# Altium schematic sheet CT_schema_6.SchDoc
size 278 x 170 mm
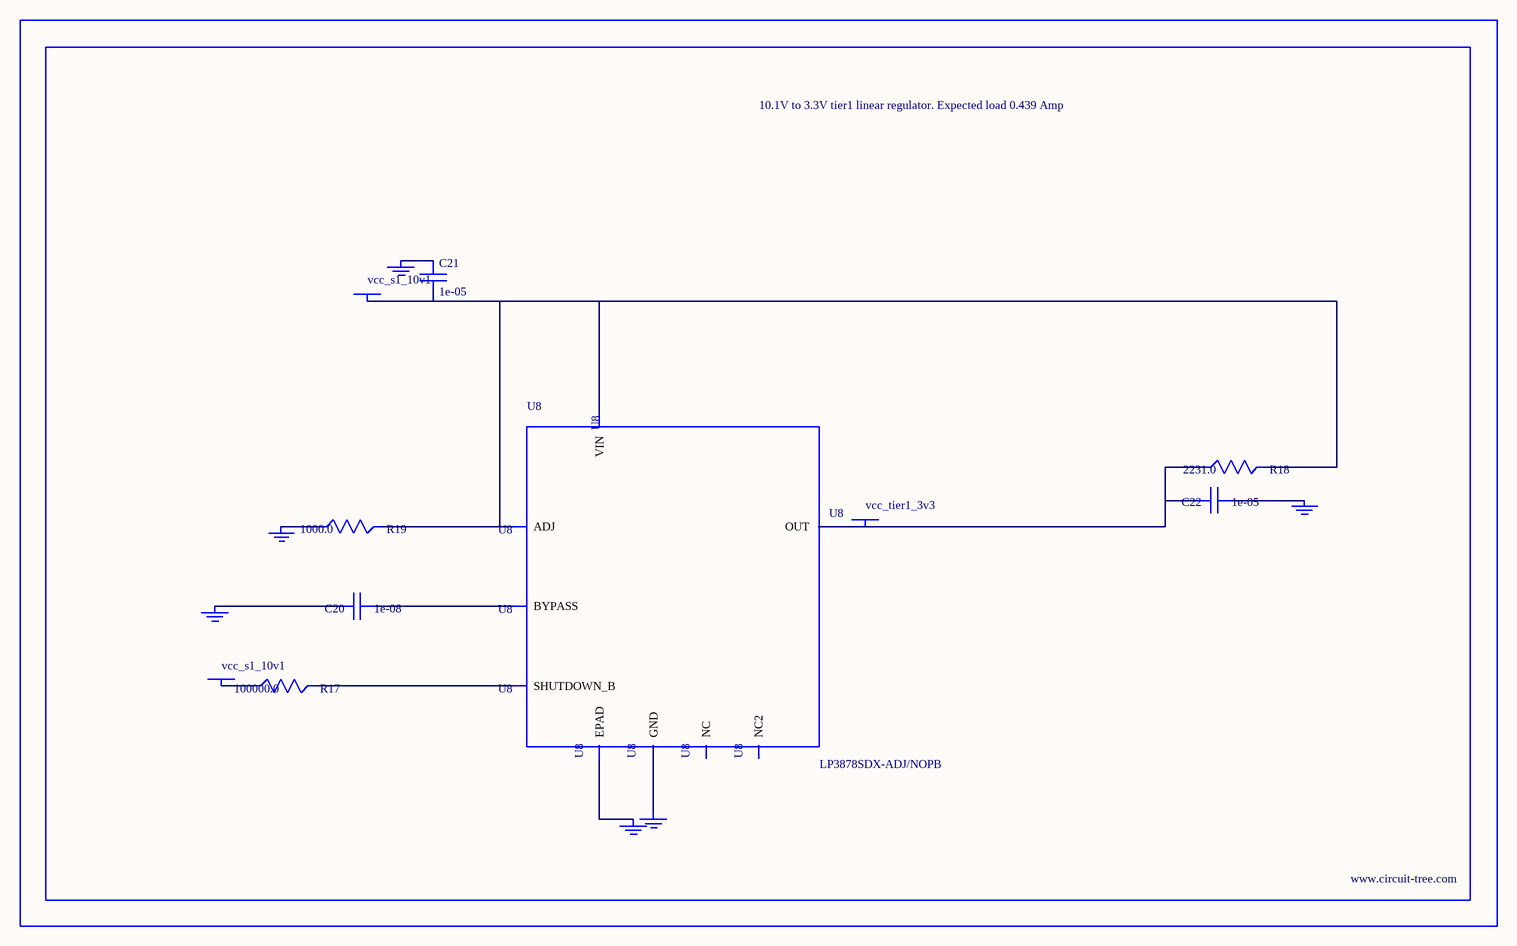
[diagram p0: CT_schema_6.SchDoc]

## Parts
BORDER5  (no value)
C20  1e-08  [C0402]
C21  1e-05  [C1206]
C22  1e-05  [C1210]
GND_INSTANCE_5_0  (no value)
GND_INSTANCE_5_1  (no value)
GND_INSTANCE_5_2  (no value)
GND_INSTANCE_5_3  (no value)
GND_INSTANCE_5_4  (no value)
GND_INSTANCE_5_5  (no value)
POWER_INSTANCE_5_0  vcc_s1_10v1
POWER_INSTANCE_5_1  vcc_s1_10v1
POWER_INSTANCE_5_2  vcc_tier1_3v3
R17  100000.0  [R0603]
R18  2231.0  [R0603]
R19  1000.0  [R0603]
U8  LP3878SDX-ADJ/NOPB  [WSON-8]

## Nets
NetC20_1: C20.1 U8.1(BYPASS)
NetC20_2: C20.2 GND_INSTANCE_5_0.0(GND)
NetC21_1: C21.1 GND_INSTANCE_5_1.0(GND)
NetC21_2: C21.2 POWER_INSTANCE_5_0.0(PWR) R18.2 R19.2 U8.4(VIN) U8.6(ADJ)
NetC22_1: C22.1 GND_INSTANCE_5_2.0(GND)
NetC22_2: C22.2 POWER_INSTANCE_5_2.0(PWR) R18.1 U8.5(OUT)
NetGND_INSTANCE_5_3_0: GND_INSTANCE_5_3.0(GND) R19.1
NetGND_INSTANCE_5_4_0: GND_INSTANCE_5_4.0(GND) U8.PAD(EPAD)
NetGND_INSTANCE_5_5_0: GND_INSTANCE_5_5.0(GND) U8.3(GND)
NetPOWER_INSTANCE_5_1_0: POWER_INSTANCE_5_1.0(PWR) R17.1
NetR17_2: R17.2 U8.8(SHUTDOWN_B)

Not connected (* = marked no-connect by the designer): U8 2(NC) 7(NC2)

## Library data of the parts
BORDER5 = BORDER_PAGE5
C20 = C0402C103K3RAC
C21 = C1206C106K3RACTU
C22 = GRM32DR61E106MA12L
GND_INSTANCE_5_0-GND_INSTANCE_5_5 = GND
POWER_INSTANCE_5_0-POWER_INSTANCE_5_2 = PWR
R17 = RC0603JR-07100KL
R18 = R18
R19 = RC0603JR-071KL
